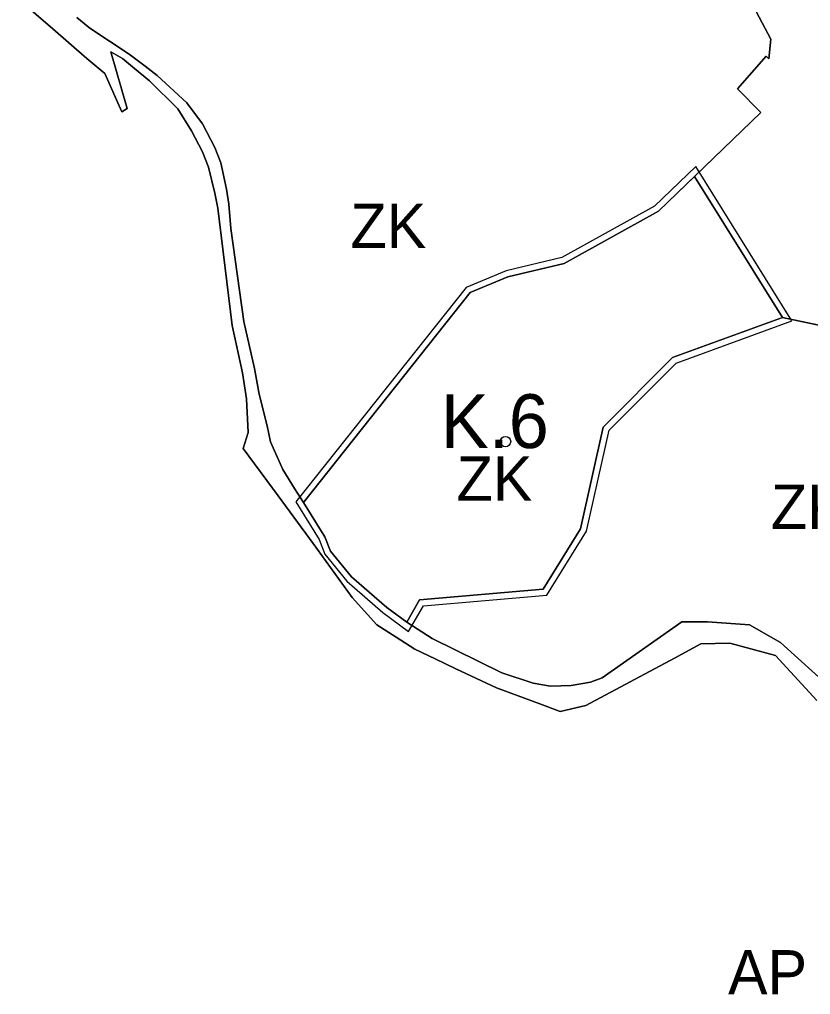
# Model space of a CAD drawing. Extents: x -555509 to -553005, y -1186756 to -1182560.
# Drawn here: x -553990.3 to -553740.6, y -1186116.2 to -1185808.2 of the extents above; entities that cross this region are included whole.
import ezdxf

# ---------------------------------------------------------------- set-up
doc = ezdxf.new("R2010")
doc.units = 0
for name, color, linetype in [('Level 26', 7, 'Continuous'), ('Level 46', 7, 'Continuous'), ('Level 56', 7, 'Continuous'), ('Level 59', 7, 'Continuous'), ('Level 63', 7, 'Continuous'), ('navrh_ZK', 7, 'Continuous'), ('OBRYS_PLOCH', 7, 'Continuous'), ('stav_AL', 7, 'Continuous'), ('stav_AP', 7, 'Continuous'), ('stav_ZK', 7, 'Continuous')]:
    doc.layers.add(name, color=color, linetype=linetype)

msp = doc.modelspace()

# ---------------------------------------------------------------- linework, layer by layer
at = {"layer": 'Level 26'}
for p, q in [((-553990.34, -1185802.14), (-553979.8, -1185811.2)), ((-553968.15, -1185811.02), (-553972.23, -1185807.6)), ((-553979.8, -1185811.2), (-553969.07, -1185820.6)), ((-553955.74, -1185819.21), (-553968.15, -1185811.02)), ((-553956.38, -1185836.31), (-553961.51, -1185818.49)), ((-553961.51, -1185818.49), (-553957.82, -1185820.6)), ((-553969.07, -1185820.6), (-553963.44, -1185825.34)), ((-553957.82, -1185820.6), (-553954.06, -1185823.69)), ((-553950.71, -1185822.99), (-553955.74, -1185819.21)), ((-553963.44, -1185825.34), (-553958.04, -1185837.42)), ((-553954.06, -1185823.69), (-553949.35, -1185827.56)), ((-553946.85, -1185825.9), (-553950.71, -1185822.99)), ((-553949.35, -1185827.56), (-553940.4, -1185836.5)), ((-553937.49, -1185834.57), (-553946.85, -1185825.9)), ((-553932.62, -1185841.17), (-553937.49, -1185834.57)), ((-553958.04, -1185837.42), (-553956.38, -1185836.31)), ((-553940.4, -1185836.5), (-553936.03, -1185843.44)), ((-553936.03, -1185843.44), (-553932.53, -1185850.02)), ((-553928.66, -1185848.69), (-553932.62, -1185841.17)), ((-553926.78, -1185853.53), (-553928.66, -1185848.69)), ((-553932.53, -1185850.02), (-553930.65, -1185854.86)), ((-553930.65, -1185854.86), (-553928.67, -1185863.05)), ((-553924.99, -1185861.78), (-553926.78, -1185853.53)), ((-553924.28, -1185866.6), (-553924.99, -1185861.78)), ((-553928.67, -1185863.05), (-553927.77, -1185867.8)), ((-553927.77, -1185867.8), (-553923.23, -1185904.86)), ((-553923.67, -1185874.2), (-553924.28, -1185866.6)), ((-553919.55, -1185903.59), (-553923.67, -1185874.2)), ((-553923.23, -1185904.86), (-553919.98, -1185919.78)), ((-553916.21, -1185918.48), (-553919.55, -1185903.59)), ((-553919.98, -1185919.78), (-553918.73, -1185928.01)), ((-553914.68, -1185926.61), (-553916.21, -1185918.48)), ((-553912.17, -1185936.62), (-553914.68, -1185926.61)), ((-553918.73, -1185928.01), (-553918.12, -1185938.67)), ((-553918.12, -1185938.67), (-553919.73, -1185943.78)), ((-553911.06, -1185941.63), (-553912.17, -1185936.62)), ((-553907.2, -1185950.33), (-553911.06, -1185941.63)), ((-553919.73, -1185943.78), (-553908.64, -1185958.71)), ((-553903.49, -1185956.33), (-553907.2, -1185950.33)), ((-553900.68, -1185960.74), (-553903.49, -1185956.33)), ((-553908.64, -1185958.71), (-553897.65, -1185973.74)), ((-553893.92, -1185971.59), (-553900.68, -1185960.74)), ((-553892.19, -1185976.11), (-553893.92, -1185971.59)), ((-553897.65, -1185973.74), (-553885.32, -1185990.74)), ((-553885.57, -1185984.25), (-553892.19, -1185976.11)), ((-553874.36, -1185993.93), (-553885.57, -1185984.25)), ((-553885.32, -1185990.74), (-553881.43, -1185995.07)), ((-553868.12, -1185998.62), (-553874.36, -1185993.93)), ((-553881.43, -1185995.07), (-553877.49, -1185999.45)), ((-553877.49, -1185999.45), (-553871.4, -1186003.28)), ((-553860.09, -1186003.76), (-553868.12, -1185998.62)), ((-553781.21, -1185998.52), (-553806.36, -1186016.14)), ((-553773.17, -1185998.47), (-553781.21, -1185998.52)), ((-553759.89, -1185999.41), (-553773.17, -1185998.47)), ((-553750.12, -1186005), (-553759.89, -1185999.41)), ((-553871.4, -1186003.28), (-553865.54, -1186007.07)), ((-553838.07, -1186014.61), (-553860.09, -1186003.76)), ((-553783.6, -1186009.94), (-553775.22, -1186005.45)), ((-553775.22, -1186005.45), (-553766.08, -1186005.22)), ((-553766.08, -1186005.22), (-553751.74, -1186009.14)), ((-553732.97, -1186020.51), (-553750.12, -1186005)), ((-553865.54, -1186007.07), (-553859.08, -1186010.2)), ((-553811.61, -1186024.94), (-553783.6, -1186009.94)), ((-553751.74, -1186009.14), (-553738.6, -1186023.35)), ((-553859.08, -1186010.2), (-553852.62, -1186013.33)), ((-553852.62, -1186013.33), (-553839.79, -1186019.36)), ((-553828.19, -1186017.87), (-553838.07, -1186014.61)), ((-553806.36, -1186016.14), (-553810.09, -1186017.51)), ((-553822.68, -1186018.8), (-553828.19, -1186017.87)), ((-553816.22, -1186018.59), (-553822.68, -1186018.8)), ((-553810.09, -1186017.51), (-553816.22, -1186018.59)), ((-553839.79, -1186019.36), (-553826.09, -1186024.32)), ((-553826.09, -1186024.32), (-553819.68, -1186026.76)), ((-553819.68, -1186026.76), (-553811.61, -1186024.94))]:
    msp.add_line(p, q, dxfattribs=at)
at = {"layer": 'Level 46'}
msp.add_circle((-553836.91, -1185941.56), 1.64, dxfattribs=at)
at = {"layer": 'Level 56'}
msp.add_lwpolyline([(-553862.82, -1185993.45), (-553823.91, -1185990.03), (-553811.32, -1185969.84), (-553804.25, -1185937.97), (-553783.09, -1185916.75), (-553746.51, -1185903.43), (-553776.89, -1185854.66), (-553789.86, -1185867.15), (-553819.14, -1185883.38), (-553836.76, -1185887.64), (-553849.36, -1185892.87), (-553903.12, -1185960.6), (-553895.72, -1185972.48), (-553893.94, -1185977.12), (-553887.01, -1185985.65), (-553875.62, -1185995.49), (-553867.52, -1186001.57)], close=True, dxfattribs=at)
at = {"layer": 'navrh_ZK'}
for p, q in [((-553749.52, -1185902.39), (-553777.28, -1185857.82)), ((-553900.68, -1185960.74), (-553893.92, -1185971.59)), ((-553893.92, -1185971.59), (-553892.19, -1185976.11)), ((-553892.19, -1185976.11), (-553885.57, -1185984.25))]:
    msp.add_line(p, q, dxfattribs=at)
for points in [[(-553777.28, -1185857.82), (-553788.67, -1185868.78), (-553818.41, -1185885.26), (-553836.14, -1185889.54), (-553848.12, -1185894.51), (-553900.68, -1185960.74)], [(-553825.07, -1185988.12), (-553813.2, -1185969.07), (-553806.08, -1185936.97), (-553784.19, -1185915.02), (-553749.52, -1185902.39)], [(-553885.57, -1185984.25), (-553874.36, -1185993.93), (-553868.12, -1185998.62)], [(-553868.12, -1185998.62), (-553864.03, -1185991.55), (-553825.07, -1185988.12)]]:
    msp.add_lwpolyline(points, dxfattribs=at)
at = {"layer": 'OBRYS_PLOCH'}
for p, q in [((-553979.8, -1185811.2), (-553990.34, -1185802.14)), ((-553972.23, -1185807.6), (-553968.15, -1185811.02)), ((-553968.15, -1185811.02), (-553972.23, -1185807.6)), ((-553969.07, -1185820.6), (-553979.8, -1185811.2)), ((-553955.74, -1185819.21), (-553968.15, -1185811.02)), ((-553753.12, -1185814.47), (-553753.81, -1185820.66)), ((-553957.82, -1185820.6), (-553961.51, -1185818.49)), ((-553961.51, -1185818.49), (-553956.38, -1185836.31)), ((-553956.38, -1185836.31), (-553961.51, -1185818.49)), ((-553969.07, -1185820.6), (-553963.44, -1185825.34)), ((-553954.06, -1185823.69), (-553957.82, -1185820.6)), ((-553950.71, -1185822.99), (-553955.74, -1185819.21)), ((-553763.69, -1185830.09), (-553754.66, -1185819.8)), ((-553754.66, -1185819.8), (-553763.69, -1185830.09)), ((-553754.66, -1185819.8), (-553753.81, -1185820.66)), ((-553753.81, -1185820.66), (-553754.66, -1185819.8)), ((-553963.44, -1185825.34), (-553958.04, -1185837.42)), ((-553949.35, -1185827.56), (-553954.06, -1185823.69)), ((-553954.06, -1185823.69), (-553949.35, -1185827.56)), ((-553950.71, -1185822.99), (-553946.85, -1185825.9)), ((-553946.85, -1185825.9), (-553950.71, -1185822.99)), ((-553940.4, -1185836.5), (-553949.35, -1185827.56)), ((-553949.35, -1185827.56), (-553940.4, -1185836.5)), ((-553946.85, -1185825.9), (-553937.49, -1185834.57)), ((-553937.49, -1185834.57), (-553946.85, -1185825.9)), ((-553763.69, -1185830.09), (-553756.31, -1185837.63)), ((-553937.49, -1185834.57), (-553932.62, -1185841.17)), ((-553932.62, -1185841.17), (-553937.49, -1185834.57)), ((-553956.38, -1185836.31), (-553958.04, -1185837.42)), ((-553958.04, -1185837.42), (-553956.38, -1185836.31)), ((-553936.03, -1185843.44), (-553940.4, -1185836.5)), ((-553940.4, -1185836.5), (-553936.03, -1185843.44)), ((-553756.31, -1185837.63), (-553777.28, -1185857.82)), ((-553932.53, -1185850.02), (-553936.03, -1185843.44)), ((-553936.03, -1185843.44), (-553932.53, -1185850.02)), ((-553932.62, -1185841.17), (-553928.66, -1185848.69)), ((-553928.66, -1185848.69), (-553932.62, -1185841.17)), ((-553928.66, -1185848.69), (-553926.78, -1185853.53)), ((-553926.78, -1185853.53), (-553928.66, -1185848.69)), ((-553930.65, -1185854.86), (-553932.53, -1185850.02)), ((-553932.53, -1185850.02), (-553930.65, -1185854.86)), ((-553928.67, -1185863.05), (-553930.65, -1185854.86)), ((-553930.65, -1185854.86), (-553928.67, -1185863.05)), ((-553926.78, -1185853.53), (-553924.99, -1185861.78)), ((-553924.99, -1185861.78), (-553926.78, -1185853.53)), ((-553749.52, -1185902.39), (-553777.28, -1185857.82)), ((-553777.28, -1185857.82), (-553749.52, -1185902.39)), ((-553924.99, -1185861.78), (-553924.28, -1185866.6)), ((-553924.28, -1185866.6), (-553924.99, -1185861.78)), ((-553927.77, -1185867.8), (-553928.67, -1185863.05)), ((-553928.67, -1185863.05), (-553927.77, -1185867.8)), ((-553923.23, -1185904.86), (-553927.77, -1185867.8)), ((-553927.77, -1185867.8), (-553923.23, -1185904.86)), ((-553924.28, -1185866.6), (-553923.67, -1185874.2)), ((-553923.67, -1185874.2), (-553924.28, -1185866.6)), ((-553923.67, -1185874.2), (-553919.55, -1185903.59)), ((-553919.55, -1185903.59), (-553923.67, -1185874.2)), ((-553919.98, -1185919.78), (-553923.23, -1185904.86)), ((-553923.23, -1185904.86), (-553919.98, -1185919.78)), ((-553919.55, -1185903.59), (-553916.21, -1185918.48)), ((-553916.21, -1185918.48), (-553919.55, -1185903.59)), ((-553749.52, -1185902.39), (-553716.55, -1185909.35)), ((-553918.73, -1185928.01), (-553919.98, -1185919.78)), ((-553919.98, -1185919.78), (-553918.73, -1185928.01)), ((-553916.21, -1185918.48), (-553914.68, -1185926.61)), ((-553914.68, -1185926.61), (-553916.21, -1185918.48)), ((-553918.12, -1185938.67), (-553918.73, -1185928.01)), ((-553918.73, -1185928.01), (-553918.12, -1185938.67)), ((-553919.73, -1185943.78), (-553918.12, -1185938.67)), ((-553918.12, -1185938.67), (-553919.73, -1185943.78)), ((-553911.06, -1185941.63), (-553907.2, -1185950.33)), ((-553907.2, -1185950.33), (-553911.06, -1185941.63)), ((-553908.64, -1185958.71), (-553919.73, -1185943.78)), ((-553919.73, -1185943.78), (-553908.64, -1185958.71)), ((-553907.2, -1185950.33), (-553903.49, -1185956.33)), ((-553903.49, -1185956.33), (-553907.2, -1185950.33)), ((-553903.49, -1185956.33), (-553900.68, -1185960.74)), ((-553900.68, -1185960.74), (-553903.49, -1185956.33)), ((-553897.65, -1185973.74), (-553908.64, -1185958.71)), ((-553908.64, -1185958.71), (-553897.65, -1185973.74)), ((-553900.68, -1185960.74), (-553893.92, -1185971.59)), ((-553893.92, -1185971.59), (-553900.68, -1185960.74)), ((-553893.92, -1185971.59), (-553892.19, -1185976.11)), ((-553892.19, -1185976.11), (-553893.92, -1185971.59)), ((-553885.32, -1185990.74), (-553897.65, -1185973.74)), ((-553897.65, -1185973.74), (-553885.32, -1185990.74)), ((-553892.19, -1185976.11), (-553885.57, -1185984.25)), ((-553885.57, -1185984.25), (-553892.19, -1185976.11)), ((-553874.36, -1185993.93), (-553885.57, -1185984.25)), ((-553881.43, -1185995.07), (-553885.32, -1185990.74)), ((-553885.32, -1185990.74), (-553881.43, -1185995.07)), ((-553868.12, -1185998.62), (-553874.36, -1185993.93)), ((-553877.49, -1185999.45), (-553881.43, -1185995.07)), ((-553881.43, -1185995.07), (-553877.49, -1185999.45)), ((-553871.4, -1186003.28), (-553877.49, -1185999.45)), ((-553877.49, -1185999.45), (-553871.4, -1186003.28)), ((-553868.12, -1185998.62), (-553860.09, -1186003.76)), ((-553860.09, -1186003.76), (-553868.12, -1185998.62)), ((-553806.36, -1186016.14), (-553781.21, -1185998.52)), ((-553781.21, -1185998.52), (-553806.36, -1186016.14)), ((-553781.21, -1185998.52), (-553773.17, -1185998.47)), ((-553773.17, -1185998.47), (-553781.21, -1185998.52)), ((-553773.17, -1185998.47), (-553759.89, -1185999.41)), ((-553759.89, -1185999.41), (-553773.17, -1185998.47)), ((-553759.89, -1185999.41), (-553750.12, -1186005)), ((-553750.12, -1186005), (-553759.89, -1185999.41)), ((-553865.54, -1186007.07), (-553871.4, -1186003.28)), ((-553871.4, -1186003.28), (-553865.54, -1186007.07)), ((-553860.09, -1186003.76), (-553838.07, -1186014.61)), ((-553838.07, -1186014.61), (-553860.09, -1186003.76)), ((-553775.22, -1186005.45), (-553783.6, -1186009.94)), ((-553783.6, -1186009.94), (-553775.22, -1186005.45)), ((-553766.08, -1186005.22), (-553775.22, -1186005.45)), ((-553775.22, -1186005.45), (-553766.08, -1186005.22)), ((-553751.74, -1186009.14), (-553766.08, -1186005.22)), ((-553766.08, -1186005.22), (-553751.74, -1186009.14)), ((-553750.12, -1186005), (-553732.97, -1186020.51)), ((-553732.97, -1186020.51), (-553750.12, -1186005)), ((-553859.08, -1186010.2), (-553865.54, -1186007.07)), ((-553865.54, -1186007.07), (-553859.08, -1186010.2)), ((-553783.6, -1186009.94), (-553811.61, -1186024.94)), ((-553811.61, -1186024.94), (-553783.6, -1186009.94)), ((-553738.6, -1186023.35), (-553751.74, -1186009.14)), ((-553751.74, -1186009.14), (-553738.6, -1186023.35)), ((-553852.62, -1186013.33), (-553859.08, -1186010.2)), ((-553859.08, -1186010.2), (-553852.62, -1186013.33)), ((-553839.79, -1186019.36), (-553852.62, -1186013.33)), ((-553852.62, -1186013.33), (-553839.79, -1186019.36)), ((-553838.07, -1186014.61), (-553828.19, -1186017.87)), ((-553828.19, -1186017.87), (-553838.07, -1186014.61)), ((-553810.09, -1186017.51), (-553806.36, -1186016.14)), ((-553806.36, -1186016.14), (-553810.09, -1186017.51)), ((-553828.19, -1186017.87), (-553822.68, -1186018.8)), ((-553822.68, -1186018.8), (-553828.19, -1186017.87)), ((-553822.68, -1186018.8), (-553816.22, -1186018.59)), ((-553816.22, -1186018.59), (-553822.68, -1186018.8)), ((-553816.22, -1186018.59), (-553810.09, -1186017.51)), ((-553810.09, -1186017.51), (-553816.22, -1186018.59)), ((-553826.09, -1186024.32), (-553839.79, -1186019.36)), ((-553839.79, -1186019.36), (-553826.09, -1186024.32)), ((-553819.68, -1186026.76), (-553826.09, -1186024.32)), ((-553826.09, -1186024.32), (-553819.68, -1186026.76)), ((-553811.61, -1186024.94), (-553819.68, -1186026.76)), ((-553819.68, -1186026.76), (-553811.61, -1186024.94))]:
    msp.add_line(p, q, dxfattribs=at)
for points in [[(-553753.81, -1185820.66), (-553753.12, -1185814.47), (-553762.29, -1185797.04), (-553784.01, -1185781.14), (-553826.51, -1185773.19), (-553905.75, -1185768.76), (-553885.33, -1185687.44), (-553881.88, -1185682.28), (-553877.28, -1185678.22), (-553871.61, -1185675.43), (-553866.15, -1185674.26), (-553858.58, -1185674.39), (-553813.14, -1185685.81), (-553754.19, -1185701.48), (-553682.62, -1185722.72), (-553674.53, -1185694.64)], [(-553784.01, -1185781.14), (-553762.29, -1185797.04), (-553753.12, -1185814.47)], [(-553990.34, -1185802.14), (-553979.8, -1185811.2), (-553969.07, -1185820.6)], [(-553968.15, -1185811.02), (-553955.74, -1185819.21), (-553950.71, -1185822.99)], [(-553961.51, -1185818.49), (-553957.82, -1185820.6), (-553954.06, -1185823.69)], [(-553958.04, -1185837.42), (-553963.44, -1185825.34), (-553969.07, -1185820.6)], [(-553900.68, -1185960.74), (-553848.12, -1185894.51), (-553836.14, -1185889.54), (-553818.41, -1185885.26), (-553788.67, -1185868.78), (-553756.31, -1185837.63), (-553763.69, -1185830.09)], [(-553777.28, -1185857.82), (-553788.67, -1185868.78), (-553818.41, -1185885.26), (-553836.14, -1185889.54), (-553848.12, -1185894.51), (-553900.68, -1185960.74)], [(-553669.55, -1185954.79), (-553716.55, -1185909.35), (-553749.52, -1185902.39), (-553784.19, -1185915.02), (-553806.08, -1185936.97), (-553813.2, -1185969.07), (-553825.07, -1185988.12), (-553864.03, -1185991.55), (-553868.12, -1185998.62)], [(-553825.07, -1185988.12), (-553813.2, -1185969.07), (-553806.08, -1185936.97), (-553784.19, -1185915.02), (-553749.52, -1185902.39)], [(-553914.68, -1185926.61), (-553912.17, -1185936.62), (-553911.06, -1185941.63)], [(-553911.06, -1185941.63), (-553912.17, -1185936.62), (-553914.68, -1185926.61)], [(-553885.57, -1185984.25), (-553874.36, -1185993.93), (-553868.12, -1185998.62)], [(-553868.12, -1185998.62), (-553864.03, -1185991.55), (-553825.07, -1185988.12)]]:
    msp.add_lwpolyline(points, dxfattribs=at)
at = {"layer": 'stav_AL'}
for p, q in [((-553754.66, -1185819.8), (-553763.69, -1185830.09)), ((-553753.81, -1185820.66), (-553754.66, -1185819.8)), ((-553777.28, -1185857.82), (-553749.52, -1185902.39))]:
    msp.add_line(p, q, dxfattribs=at)
for points in [[(-553682.62, -1185722.72), (-553754.19, -1185701.48), (-553813.14, -1185685.81), (-553858.58, -1185674.39), (-553866.15, -1185674.26), (-553871.61, -1185675.43), (-553877.28, -1185678.22), (-553881.88, -1185682.28), (-553885.33, -1185687.44), (-553905.75, -1185768.76), (-553826.51, -1185773.19), (-553784.01, -1185781.14), (-553762.29, -1185797.04), (-553753.12, -1185814.47), (-553753.81, -1185820.66)], [(-553763.69, -1185830.09), (-553756.31, -1185837.63), (-553777.28, -1185857.82)], [(-553749.52, -1185902.39), (-553716.55, -1185909.35), (-553669.55, -1185954.79)]]:
    msp.add_lwpolyline(points, dxfattribs=at)
at = {"layer": 'stav_AP'}
for p, q in [((-553961.51, -1185818.49), (-553956.38, -1185836.31)), ((-553949.35, -1185827.56), (-553954.06, -1185823.69)), ((-553940.4, -1185836.5), (-553949.35, -1185827.56)), ((-553936.03, -1185843.44), (-553940.4, -1185836.5)), ((-553932.53, -1185850.02), (-553936.03, -1185843.44)), ((-553930.65, -1185854.86), (-553932.53, -1185850.02)), ((-553928.67, -1185863.05), (-553930.65, -1185854.86)), ((-553927.77, -1185867.8), (-553928.67, -1185863.05)), ((-553923.23, -1185904.86), (-553927.77, -1185867.8)), ((-553919.98, -1185919.78), (-553923.23, -1185904.86)), ((-553918.73, -1185928.01), (-553919.98, -1185919.78)), ((-553918.12, -1185938.67), (-553918.73, -1185928.01)), ((-553919.73, -1185943.78), (-553918.12, -1185938.67)), ((-553908.64, -1185958.71), (-553919.73, -1185943.78)), ((-553897.65, -1185973.74), (-553908.64, -1185958.71)), ((-553885.32, -1185990.74), (-553897.65, -1185973.74)), ((-553881.43, -1185995.07), (-553885.32, -1185990.74)), ((-553877.49, -1185999.45), (-553881.43, -1185995.07)), ((-553871.4, -1186003.28), (-553877.49, -1185999.45)), ((-553865.54, -1186007.07), (-553871.4, -1186003.28)), ((-553775.22, -1186005.45), (-553783.6, -1186009.94)), ((-553766.08, -1186005.22), (-553775.22, -1186005.45)), ((-553751.74, -1186009.14), (-553766.08, -1186005.22)), ((-553859.08, -1186010.2), (-553865.54, -1186007.07)), ((-553783.6, -1186009.94), (-553811.61, -1186024.94)), ((-553738.6, -1186023.35), (-553751.74, -1186009.14)), ((-553852.62, -1186013.33), (-553859.08, -1186010.2)), ((-553839.79, -1186019.36), (-553852.62, -1186013.33)), ((-553826.09, -1186024.32), (-553839.79, -1186019.36)), ((-553819.68, -1186026.76), (-553826.09, -1186024.32)), ((-553811.61, -1186024.94), (-553819.68, -1186026.76))]:
    msp.add_line(p, q, dxfattribs=at)
for points in [[(-553963.44, -1185825.34), (-553969.07, -1185820.6), (-553979.8, -1185811.2), (-553990.34, -1185802.14)], [(-553954.06, -1185823.69), (-553957.82, -1185820.6), (-553961.51, -1185818.49)], [(-553956.38, -1185836.31), (-553958.04, -1185837.42), (-553963.44, -1185825.34)]]:
    msp.add_lwpolyline(points, dxfattribs=at)
at = {"layer": 'stav_ZK'}
for p, q in [((-553972.23, -1185807.6), (-553968.15, -1185811.02)), ((-553763.69, -1185830.09), (-553754.66, -1185819.8)), ((-553754.66, -1185819.8), (-553753.81, -1185820.66)), ((-553950.71, -1185822.99), (-553946.85, -1185825.9)), ((-553946.85, -1185825.9), (-553937.49, -1185834.57)), ((-553937.49, -1185834.57), (-553932.62, -1185841.17)), ((-553932.62, -1185841.17), (-553928.66, -1185848.69)), ((-553928.66, -1185848.69), (-553926.78, -1185853.53)), ((-553926.78, -1185853.53), (-553924.99, -1185861.78)), ((-553924.99, -1185861.78), (-553924.28, -1185866.6)), ((-553924.28, -1185866.6), (-553923.67, -1185874.2)), ((-553923.67, -1185874.2), (-553919.55, -1185903.59)), ((-553919.55, -1185903.59), (-553916.21, -1185918.48)), ((-553916.21, -1185918.48), (-553914.68, -1185926.61)), ((-553911.06, -1185941.63), (-553907.2, -1185950.33)), ((-553907.2, -1185950.33), (-553903.49, -1185956.33)), ((-553903.49, -1185956.33), (-553900.68, -1185960.74)), ((-553868.12, -1185998.62), (-553860.09, -1186003.76)), ((-553806.36, -1186016.14), (-553781.21, -1185998.52)), ((-553781.21, -1185998.52), (-553773.17, -1185998.47)), ((-553773.17, -1185998.47), (-553759.89, -1185999.41)), ((-553759.89, -1185999.41), (-553750.12, -1186005)), ((-553860.09, -1186003.76), (-553838.07, -1186014.61)), ((-553750.12, -1186005), (-553732.97, -1186020.51)), ((-553838.07, -1186014.61), (-553828.19, -1186017.87)), ((-553810.09, -1186017.51), (-553806.36, -1186016.14)), ((-553828.19, -1186017.87), (-553822.68, -1186018.8)), ((-553822.68, -1186018.8), (-553816.22, -1186018.59)), ((-553816.22, -1186018.59), (-553810.09, -1186017.51))]:
    msp.add_line(p, q, dxfattribs=at)
for points in [[(-553753.81, -1185820.66), (-553753.12, -1185814.47), (-553762.29, -1185797.04), (-553784.01, -1185781.14), (-553826.51, -1185773.19), (-553905.75, -1185768.76), (-553885.33, -1185687.44), (-553881.88, -1185682.28), (-553877.28, -1185678.22), (-553871.61, -1185675.43), (-553866.15, -1185674.26), (-553858.58, -1185674.39), (-553813.14, -1185685.81), (-553754.19, -1185701.48), (-553682.62, -1185722.72), (-553674.53, -1185694.64)], [(-553968.15, -1185811.02), (-553955.74, -1185819.21), (-553950.71, -1185822.99)], [(-553900.68, -1185960.74), (-553848.12, -1185894.51), (-553836.14, -1185889.54), (-553818.41, -1185885.26), (-553788.67, -1185868.78), (-553756.31, -1185837.63), (-553763.69, -1185830.09)], [(-553669.55, -1185954.79), (-553716.55, -1185909.35), (-553749.52, -1185902.39), (-553784.19, -1185915.02), (-553806.08, -1185936.97), (-553813.2, -1185969.07), (-553825.07, -1185988.12), (-553864.03, -1185991.55), (-553868.12, -1185998.62)], [(-553914.68, -1185926.61), (-553912.17, -1185936.62), (-553911.06, -1185941.63)]]:
    msp.add_lwpolyline(points, dxfattribs=at)

# ---------------------------------------------------------------- texts
at = {"layer": 'Level 46'}
msp.add_text('K.6', height=17, dxfattribs=at).set_placement((-553857.37, -1185943.59))
at = {"layer": 'Level 59'}
for s, p in [('ZK', (-553885.86, -1185880.38)), ('ZK', (-553753.14, -1185969.12)), ('AP', (-553766.68, -1186116.17))]:
    msp.add_text(s, height=14, dxfattribs=at).set_placement(p)
at = {"layer": 'Level 63'}
msp.add_text('ZK', height=14, dxfattribs=at).set_placement((-553852.36, -1185960.24))

doc.saveas('drawing.dxf')
